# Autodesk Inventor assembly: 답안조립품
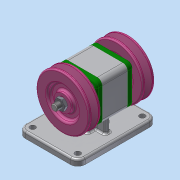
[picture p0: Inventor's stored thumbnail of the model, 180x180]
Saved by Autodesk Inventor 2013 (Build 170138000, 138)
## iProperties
Created: 2020-11
Part Number: 답안조립품
Document SubType Name: Assembly
Designer: Administrator
Author: Administrator
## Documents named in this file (10)
- C:\Users\Administrator\Desktop\701106V1027\답안조립품.iam
- C:\Users\Administrator\Desktop\701106V1027\본체.ipt
- C:\Users\Administrator\Desktop\701106V1027\베어링 6004.ipt
- C:\Users\Administrator\Desktop\701106V1027\오일 실 17 30 5.ipt
- C:\Users\Administrator\Desktop\701106V1027\커버.ipt
- C:\Users\Administrator\Desktop\701106V1027\볼트 M4.ipt
- C:\Users\Administrator\Desktop\701106V1027\축.ipt
- C:\Users\Administrator\Desktop\701106V1027\키 5 x 5 x 12.ipt
- C:\Users\Administrator\Desktop\701106V1027\V-벨트풀리.ipt
- C:\Users\Administrator\Desktop\701106V1027\너트 M10x1.ipt
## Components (2 placed, 1 different names)
1. V-벨트풀리:1 — 각도:3
2. V-벨트풀리:2 — 각도:4
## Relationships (2: Angle 2)
- 각도:3 [Angle]: V-벨트풀리:1
- 각도:4 [Angle]: V-벨트풀리:2
